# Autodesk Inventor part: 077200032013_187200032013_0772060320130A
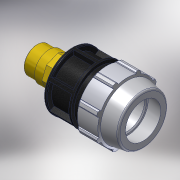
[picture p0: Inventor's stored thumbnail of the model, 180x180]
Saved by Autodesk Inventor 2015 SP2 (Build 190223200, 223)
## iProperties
Created: 2017-02
Part Number: 077200032013_187200032013_0772060320130A
Material: PVC-Piping
Description: PLASSON MALE ADAPTOR INTEGRAL BRASS THREAD 32-1.1/4"
Document SubType Name: Modeling
Designer: KIM
Mass: 92.6774 g
Surface Area: 199.44 cm^2
Volume: 66.1981 cm^3
Density: 1.4 g/cm^3
Appearance: PTFE
Author: KIM
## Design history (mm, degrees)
derived "07720.ipt"
feature "Solid1::07720.ipt"
tag "TaggingFeature1"
body "Solid1"
other parameters: "d2" = 32, "d4" = 20.28571, "d5" = 20.28571, "d7" = 64, "d8" = 48, "d9" = 20.28571, "d11" = 4.05714, "d12" = 51.2, "d13" = 120 deg, "d14" = 48, "d15" = 10 deg, "d16" = 57.6, "d18" = 1.6, "d19" = 35 deg, "d20" = 17.5 deg, "d21" = 59.52, "d23" = 0, "d25" = 360 deg, "d27" = 1.28, "d34" = 3.2, "d36" = 0, "d42" = 28.4, "d43" = 1.92, "d46" = 0.96, "d49" = 83, "d51" = 142, "d53" = 0.64, "d55" = 360 deg, "d59" = 28.4, "d60" = 41.91, "d61" = 46.101, "d62" = 22, "d63" = 47.33333, "d64" = 29.337, "d65" = 142, "d66" = 13.7482, "d67" = 0, "d68" = 0.64, "d71" = 30 deg, "d72" = 37.719, "d_" = 32, "E_" = 64, "H_" = 142, "l_" = 83, "l_2" = 22, "R_" = 41.91, "d73" = 22.91366
